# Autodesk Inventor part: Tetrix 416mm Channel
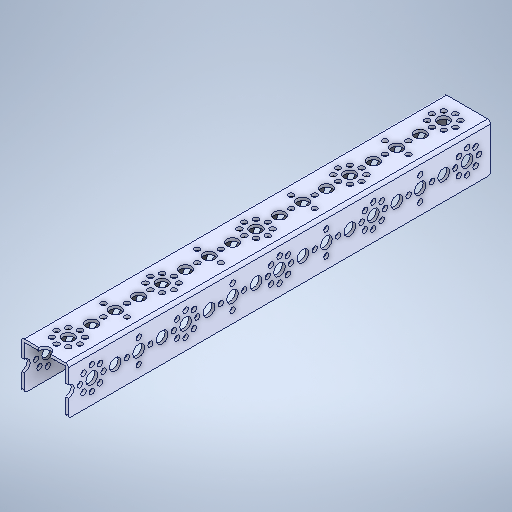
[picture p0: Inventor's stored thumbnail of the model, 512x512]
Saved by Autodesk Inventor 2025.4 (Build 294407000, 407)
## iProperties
Created: 2021-10
Part Number: Tetrix 416mm Channel
Material: Genérico
Document SubType Name: Modeling
Designer: usuario
Density: 1 g/cm^3
Appearance: Valor por defecto
Sending System: SolidWorks 2016
Last Author: LENOVO
Last Saved: 2021-10-21
Author: usuario
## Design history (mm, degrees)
fillet "Fillet1"
node "Plane1"
node "Edición directa1"
node "Sólido1"
feature "Desplazar1" dims "d2" = -128
other parameters: "d0" = 0, "d1" = 0
